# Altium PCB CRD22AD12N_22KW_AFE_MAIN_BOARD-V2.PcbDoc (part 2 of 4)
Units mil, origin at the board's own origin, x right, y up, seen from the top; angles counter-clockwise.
Board outline 14411 x 7330.3 mil, 4 copper layers (TOP, GND02, POWER03, BOTTOM), stack 78.531 mil thick; 589 components, 281 nets, 1401 pads, 282 vias.
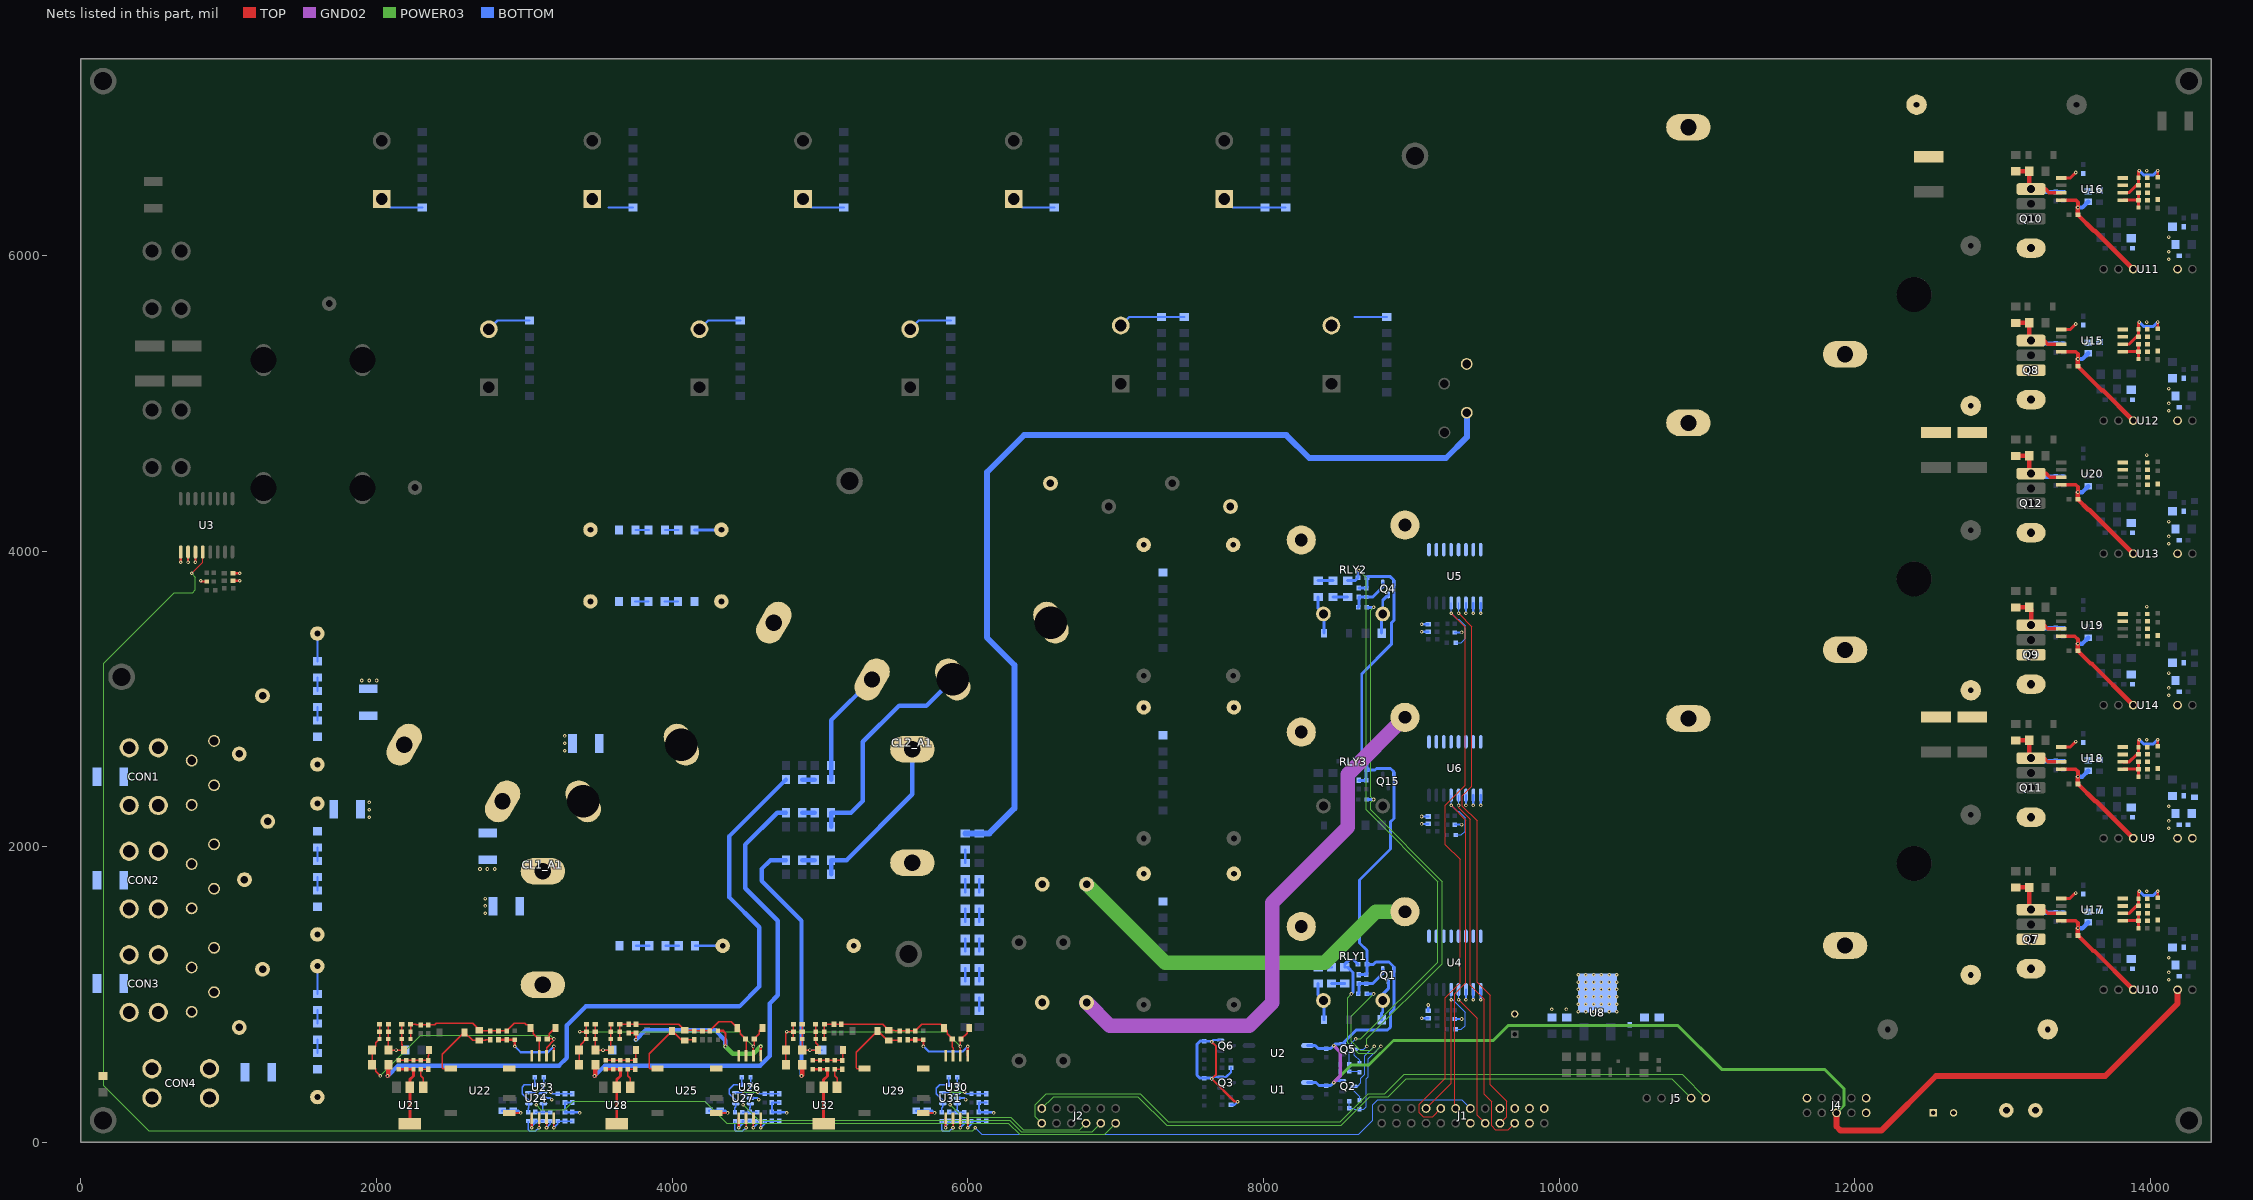
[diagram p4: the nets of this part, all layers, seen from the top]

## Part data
C1 C2 C3 C4 C5 C6 C37 C38 C39 C40 C41 C42 C43 C44 C56 C57 C58 C59 C60 C61 C62 C63 C64 C65 C66 C67 C68 C69 C70 C71 C72 C73 C74 C75 C76 C77 C78 C79 C80 C81 C82 C83 C84 C85 C86 C87 C88 C89 C90 C91 C92 C93 C94 C95 C96 C97 C98 C99 C100 C101 C102 C103 C104 C105 C106 C107 C108 C109 C112 C113 C114 C115 C116 C117 C119 C120 C121 C122 C123 C124 C126 C127 C128 C129 C130 C131 C133 C134 C135 C136 C137 C138 C140 C141 C142 C143 C144 C145 C147 C148 C149 C150 C151 C152 C212 C213 XC1 XC2 XC3 XC4 XC5 XC6 XC7 XC8 XC9 XC10 XC11 XC12 YC1 YC2 YC4 YC5 YC7 YC9 YC10 YC11: library part "CAP NP"
C7 C8 C9 C19 C20 C21 C32 C33 C34 C35 C36 C45 C46 C47 C48 C49 C50 C51 C52 C53 C54 C111 C118 C125 C132 C139 C146 C153 C154 C155 C156 C157 C158 C159 C160 C161 C162 C163 C164 C165 C166 C167 C168 C169 C170 C171 C172 C173 C174 C175 C176 C177 C178 C179 C180 C181 C182 C183 C184 C185 C186 C187 C188 C189 C190 C191 C192 C193 C194 C195 C196 C197 C198 C199 C200 C201 C202 C203 C204 C205 C206 C207 C208 C209 C210 C214 C215 C216 C217 C218 C219: library part "CAP NP_Dup1"
C10 C11 C13 C16 C17 C23 C24 C27 C28 C31 C55 C110: library part "CAP POL"
CL1: library part "TRNSFMR 67125450_0"
CL1_A1 CL2_A1: library part 126LNS_5
CON1 CON2 CON3 CON4 CON5 CON6: library part Connecter
D1 D2 D12 D13 D14 D15 D16 D17 D18: library part DIODE_0
D3 D5 D6 D8 D9 D11: library part BAS21/SOT_1
D4 D7 D10: library part "DIODE ZENER_0"
F1 F2 F3 F4 F5 F6 F7 F8: library part FUSE_0
J1: library part CON24A
J2: library part CON12A
J3: library part CON2
J4: library part CON10A
J5: library part CON5
L2 L3 L4: library part 126LNS_1
MT1 MT2 MT3 TP1 TP2: library part CON1_2
Q1 Q2 Q3 Q4 Q5 Q6 Q15: library part 2N7002/SOT
Q7 Q8 Q9 Q10 Q11 Q12: library part C3M0065090J_4
R1 R2 R3 R4 R5 R6 R7 R8 R9 R10 R11 R12 R13 R14 R15 R16 R17 R18 R19 R20 R21 R22 R23 R24 R25 R26 R27: library part R_2
R28 R29 R33 R34 R35 R36 R37 R38 R43 R44 R45 R46 R50 R51 R52 R53 R54 R55 R56 R57 R58 R59 R61 R62 R63 R64 R65 R66 R67 R68 R72 R73 R77 R78 R79 R80 R81 R83 R84 R89 R90 R92 R93 R94 R111 R112 R113 R114 R115 R116 R118 R119 R122 R123 R126 R127 R130 R131 R134 R136 R138 R139 R141 R142 R143 R144 R145 R146 R147 R148 R149 R150 R151 R152 R153 R154 R155 R156 R157 R158 R159 R160 R161 R162 R163 R164 R165 R166 R167 R168 R169 R170 R171 R172 R173 R174 R175 R176 R177 R178 R179 R181 R183 R184 R185 R186 R187 R188 R189 R190 R191 R198 R199 R200 R201 R202 R204 R205 R206 R207 R208 R209 R210 R211 R212 R213 R214 R215 R216 R217 R218 R219 R220 R221 R222 R223 R224 R225 R226 R227 R228 R229 R230 R231 R232 R233 R234 R235 R236 R237 R238 R239 R240 R241 R242 R243 R244 R245 R264 R265 R266 R267: library part RESISTOR
R42 R60 R203: library part RESISTOR_Dup1
R69 R70 R71 R74 R75 R76 R82 R85 R86 R87 R88 R91 R95 R96 R97 R98 R99 R100 R101 R102 R103 R104 R105 R106 R107 R108 R109 R110 R117 R120 R121 R124 R125 R128 R129 R132 R133 R135 R137 R140 R258 R259 R260 R261 R262 R263: library part R
RLY1 RLY2 RLY3: library part "RELAY SPST_1"
RV1 RV2 RV3 RV4 RV5 RV6 VAR1 VAR2 VAR3: library part VARISTOR
U1 U2: library part LEU169_TCLT1003_SOP-4L
U3 U4 U5 U6: library part MCR1101_0
U7 U8: library part MC78L05F-TP
U9 U10 U11 U12 U13 U14: library part E1212S-2WR2_3
U15 U16 U17 U18 U19 U20: library part UCC5350MC
U21 U28 U32: library part LT3092EST_SOT223_5
U22 U25 U29: library part PS_B0505XT
U23 U26 U30: library part 24C16BT-I/SN_3
U24 U27 U31: library part MCP6031
YC3 YC6 YC8: library part CAP

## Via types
v1: diameter 24/24/24/24 (per signal layer), hole 12, TOP to BOTTOM, tented both sides, 282 vias

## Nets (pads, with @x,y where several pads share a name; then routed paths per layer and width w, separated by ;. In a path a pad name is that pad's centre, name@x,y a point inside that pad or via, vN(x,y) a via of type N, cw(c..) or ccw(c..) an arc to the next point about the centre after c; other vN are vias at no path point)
-3V_PFCHA: C71.2 C72.2 C129.2 C131.2 U10.5 U17.8 | length 817.5
  TOP w25: U17.8@13396.68,1500 13495.34,1500 13510.26,1485.08 v1(13510.26,1450)
  TOP w30: v1(13510.26,1450) C131.2@13510.26,1400 13615.11,1295.15 13622.17,1295.15 U10.5@13884.25,1033.07
  BOTTOM w30: v1(13510.26,1450) 13540.38,1450 C129.2@13580.34,1489.96
-3V_PFCHB: C88.2 C90.2 C115.2 C117.2 U12.5 U15.8 | length 817.5
  TOP w25: U15.8@13396.68,5350 13495.34,5350 13510.26,5335.08 v1(13510.26,5300)
  TOP w30: v1(13510.26,5300) C117.2@13510.26,5250 13670.26,5090 13677.32,5090 U12.5@13884.25,4883.07
  BOTTOM w30: v1(13510.26,5300) 13540.38,5300 C115.2@13580.34,5339.96
-3V_PFCHC: C106.2 C108.2 C143.2 C145.2 U14.5 U19.8 | length 813.8
  TOP w25: U19.8@13396.68,3425 13489.04,3425 13510.26,3403.79 v1(13510.26,3375)
  TOP w30: v1(13510.26,3375) C145.2@13510.26,3325 13595.26,3240 13602.32,3240 U14.5@13884.25,2958.07
  BOTTOM w30: v1(13510.26,3375) 13540.38,3375 C143.2@13580.34,3414.96
-3V_PFCLA: C70.2 C73.2 C136.2 C138.2 U9.5 U18.8 | length 817.5
  TOP w25: U18.8@13396.68,2525 13495.34,2525 13510.26,2510.08 v1(13510.26,2475)
  TOP w30: v1(13510.26,2475) C138.2@13510.26,2425 13627.62,2307.64 13634.68,2307.64 U9.5@13884.25,2058.07
  BOTTOM w30: v1(13510.26,2475) 13540.38,2475 C136.2@13580.34,2514.96
-3V_PFCLB: C89.2 C91.2 C122.2 C124.2 U11.5 U16.8 | length 817.5
  TOP w25: U16.8@13396.68,6375 13495.34,6375 13510.26,6360.08 v1(13510.26,6325)
  TOP w30: v1(13510.26,6325) C124.2@13510.26,6275 13617.62,6167.64 13624.68,6167.64 U11.5@13884.25,5908.07
  BOTTOM w30: v1(13510.26,6325) 13540.38,6325 C122.2@13580.34,6364.96
-3V_PFCLC: C107.2 C109.2 C150.2 C152.2 U13.5 U20.8 | length 817.5
  TOP w25: U20.8@13396.68,4450 13495.34,4450 13510.26,4435.08 v1(13510.26,4400)
  TOP w30: v1(13510.26,4400) C152.2@13510.26,4350 13580.12,4280.14 13587.18,4280.14 U13.5@13884.25,3983.07
  BOTTOM w30: v1(13510.26,4400) 13540.38,4400 C150.2@13580.34,4439.96
AC_LA: CL2_A1.6 R21.2 R28.1 R266.1 RLY1.3 RV1.2 XC9.1 XC10.1 | length 792.3
  BOTTOM w30: R28.1@5075.12,2455 R266.1@5075.12,2550 5075.12,2855.36 CL2_A1.6@5352.24,3132.48
AC_LA1: RLY1.4 RV2.1 U4.1 U4.2 U4.3 U4.4 | length 2516.8
  POWER03 w100: RV2.1@6803.74,1746.85 7335.59,1215 8415,1215 8761.07,1561.07 RLY1.4@8956.88,1561.07
AC_LA_ADC: J1.15 U4.12 | length 979.3
  TOP w6: v1(9320,965) 9445,840 9445,185 J1.15@9500,130
  BOTTOM w6: v1(9320,965) U4.12@9320,1034.76
AC_LA_OC: J1.8 R100.2 U4.13 | length 1170.2
  TOP w6: J1.8@9100,230 9270,400 v1(9270,965)
  BOTTOM w6: U4.13@9270,1034.76 v1(9270,965) 9280,965 9365,880 9365,791 9339,765 R100.2@9299.92,765
AC_LA_SAMP: R29.2 R146.1 | length 4615.9
  TOP w30: v1(2075,450) 2080.12,455.12 R146.1@2080.12,525
  BOTTOM w30: v1(2075,450) 2145,520 3235,520 3288,573 3288,793 3415,920 4455,920 4590,1055 4590,1455 4385,1660 4385,2070.12 R29.2@4769.88,2455
AC_LAB_G: C157.1 C158.1 C159.1 C160.1 C161.1 C164.1 C166.2 C171.2 D4.1 R155.1 R156.1 U22.3 U23.3 U23.4 | length 1187.4
  TOP w10: R155.1@2229.92,700 R156.1@2229.92,750 C171.2@2229.92,800 2265,800 2270.08,794.92 C159.1@2299.99,794.92 C160.1@2350,794.92 2394.92,794.92 2405,805 2650.04,805 2700.12,754.92 C164.1@2769.99,754.92 C158.1@2825,754.92 C157.1@2880,754.92 2930.08,805 3004.21,805 3012.85,796.36 3025.27,796.36 3040.35,781.28 D4.1@3040.35,775 3060,755.35 3060,735.08 C166.2@3095.08,700 3099.84,695.24 U23.3@3099.84,586.52
AC_LAB_SENSE: C166.1 C167.1 C168.1 D4.2 R146.2 R152.2 R153.2 U23.2 | length 1969.9
  TOP w10: C167.1@2020.08,800 C168.1@2020.08,750 R153.2@2020.08,700 1995,674.92 1995,650.12 R152.2@1969.88,625 R146.2@1969.88,525 1995,499.88 1995,480 v1(2025,450) ; U23.2@3149.84,586.52 3149.84,639.84 3200,690 v1(3200,700) C166.1@3154.92,700 3170,715.08 3170,735.35 D4.2@3209.65,775
  POWER03 w6: v1(2025,450) 2300,725 3175,725 v1(3200,700)
AC_LAB_SENSE_ADC: C214.2 J2.2 R154.2 U24.1 | length 4300
  POWER03 w6: v1(3080,255) 3112.5,222.5 3272.5,222.5 3330,280 4220,280 4370,130 6275,130 6350,55 6925,55 J2.2@7000,130
  BOTTOM w10: v1(3080,255) 3080,310 3107.4,337.4 U24.1@3129.21,337.4 3129.92,338.11 C214.2@3129.92,390 R154.2@3129.92,440
AC_LAP: L2.3 U4.5 U4.6 U4.7 U4.8
AC_LB: CL2_A1.4 R12.2 R37.1 R264.1 RLY2.3 RV3.2 XC6.1 XC11.1 | length 1525.8
  BOTTOM w30: R264.1@5075.12,2135 R37.1@5075.12,2230 5210,2230 5290,2310 5290,2710 5535,2955 5720.28,2955 CL2_A1.4@5897.76,3132.48
AC_LB1: RLY2.4 RV4.1 U5.1 U5.2 U5.3 U5.4
AC_LB_ADC: J1.17 U5.12 | length 3726.9
  TOP w6: v1(9320,3580) 9410,3490 9410,2410 9345,2345 9345,2275 9445,2175 9445,1085 9535,995 9535,390 9645,280 9645,175 J1.17@9600,130
  BOTTOM w6: v1(9320,3580) U5.12@9320,3649.76
AC_LB_OC: J1.10 R105.2 U5.13 | length 4173.6
  TOP w6: J1.10@9200,230 9145,175 9080,175 9055,200 9055,260 9230,435 9230,980 9330,1080 9330,1915 9230,2015 9230,2280 9365,2415 9365,3485 v1(9270,3580)
  BOTTOM w6: U5.13@9270,3649.76 v1(9270,3580) 9310,3540 9320,3540 9365,3495 9365,3406 9339,3380 R105.2@9299.92,3380
AC_LB_SAMP: R38.2 R163.1 | length 3225.9
  TOP w30: v1(3475,450) 3480.12,455.12 R163.1@3480.12,525
  BOTTOM w30: v1(3475,450) 3545,520 4595,520 4660,585 4660,940 4715,995 4715,1500 4495,1720 4495,2015 4710,2230 R38.2@4769.88,2230
AC_LBC_G: C172.1 C173.1 C174.1 C177.1 C180.2 C181.1 C182.1 C193.2 D7.1 R175.1 R176.1 U25.3 U26.3 U26.4 | length 1168.7
  TOP w10: R175.1@3644.92,700 C193.2@3644.92,800 3704.92,800 C172.1@3704.99,799.92 C173.1@3755,799.92 4045.12,799.92 C174.1@4085,760.04 4144.88,760.04 C177.1@4149.99,754.92 C182.1@4205,754.92 C181.1@4254.99,754.92 4315.08,815 4400.35,815 D7.1@4440.35,775 4460,755.35 4460,735.08 4499.84,695.24 U26.3@4499.84,586.52
AC_LBC_SENSE: C180.1 C186.1 C187.1 D7.2 R163.2 R169.2 R170.2 U26.2 | length 1770.4
  TOP w10: R163.2@3369.88,525 R169.2@3369.88,625 3380,635.12 3380,659.92 R170.2@3420.08,700 C187.1@3420.08,750 ; v1(3375,750) C187.1@3420.08,750 ; C186.1@3420.08,800 C187.1@3420.08,750 ; U26.2@4549.84,586.52 v1(4549.84,650) 4554.92,655.08 C180.1@4554.92,700 4590,735.08 4590,755.35 D7.2@4609.65,775
  POWER03 w6: v1(3375,750) 4449.84,750 v1(4549.84,650)
AC_LBC_SENSE_ADC: C217.2 J2.4 R164.2 U27.1 | length 2736.2
  POWER03 w6: v1(4480,255) 4585,150 6283.28,150 6362.28,71 6841,71 J2.4@6900,130
  BOTTOM w10: v1(4480,255) 4480,305 4512.4,337.4 U27.1@4529.21,337.4 4529.92,338.11 C217.2@4529.92,390 R164.2@4529.92,440
AC_LBP: L3.3 U5.5 U5.6 U5.7 U5.8
AC_LC: CL2_A1.2 R3.2 R45.1 R265.1 RLY3.3 RV6.2 XC3.1 XC12.1 | length 1134.2
  BOTTOM w30: R265.1@5075.12,1815 R45.1@5075.12,1910 5180,1910 5625,2355 CL2_A1.2@5625,2660.04
AC_LC1: RLY3.4 RV5.1 U6.1 U6.2 U6.3 U6.4 | length 3688.2
  GND02 w100: RV5.1@6803.74,946.85 6961.59,789 7903,789 8060,946 8060,1622 8570,2132 8570,2489.18 RLY3.4@8956.88,2876.06
AC_LC_ADC: J1.19 U6.12 | length 2514
  TOP w6: v1(9320,2280) 9320,2265 9400,2185 9400,1065 9495,970 9495,325 9545,275 9545,111.5 9569,87.5 9657.5,87.5 J1.19@9700,130
  BOTTOM w6: v1(9320,2280) U6.12@9320,2349.76
AC_LC_OC: J1.12 R108.2 U6.13 | length 2489.4
  TOP w6: v1(9270,2280) 9370,2180 9370,1080 9295,1005 9295,235 J1.12@9300,230
  BOTTOM w6: U6.13@9270,2349.76 v1(9270,2280) 9310,2240 9320,2240 9365,2195 9365,2106 9339,2080 R108.2@9299.92,2080
AC_LC_SAMP: R46.2 R181.1 | length 1778.7
  TOP w30: v1(4875,450) 4880.12,455.12 R181.1@4880.12,525
  BOTTOM w30: R46.2@4769.88,1910 4665,1910 4605,1850 4605,1770 4875,1500 v1(4875,450)
AC_LCA_G: C188.1 C189.1 C190.1 C194.1 C197.2 C198.1 C199.1 C203.2 D10.1 R189.1 R190.1 U29.3 U30.3 U30.4 | length 1171.3
  TOP w10: R189.1@5029.92,700 R190.1@5029.92,750 C203.2@5029.92,800 5094.92,800 C198.1@5094.99,799.92 C199.1@5145,799.92 5425.12,799.92 C190.1@5465,760.04 5503.07,760.04 5508.19,754.92 C189.1@5595,754.92 C188.1@5644.99,754.92 5690.08,800 5815.35,800 D10.1@5840.35,775 5860,755.35 5860,735.08 C197.2@5895.08,700 5895.08,644.92 5899.84,640.16 U30.3@5899.84,586.52
AC_LCA_SENSE: C197.1 C201.1 C202.1 D10.2 R181.2 R187.2 R188.2 U30.2 | length 1801.7
  TOP w10: R181.2@4769.88,525 R187.2@4769.88,625 4769.88,744.88 v1(4775,750) C202.1@4820.08,750 ; R188.2@4820.08,700 C202.1@4820.08,750 ; C201.1@4820.08,800 C202.1@4820.08,750 ; U30.2@5949.84,586.52 v1(5949.84,650) 5949.84,694.92 C197.1@5954.92,700 5995,740.08 5995,760.35 D10.2@6009.65,775
  POWER03 w6: v1(4775,750) 5849.84,750 v1(5949.84,650)
AC_LCA_SENSE_ADC: C219.2 J2.6 R179.2 U31.1 | length 1225.4
  POWER03 w6: v1(5880,255) 5965,170 6291.57,170 6374.07,87.5 6757.5,87.5 J2.6@6800,130
  BOTTOM w10: v1(5880,255) 5880,310 5907.4,337.4 U31.1@5929.21,337.4 5929.21,389.29 C219.2@5929.92,390 R179.2@5929.92,440
AC_LCP: L4.3 U6.5 U6.6 U6.7 U6.8
AGND: C3.2 C6.2 C37.2 C38.2 C39.2 C40.2 C41.2 C42.2 C43.2 C44.2 C47.1 C48.1 C52.1 C53.1 C54.1 C55.2 C111.2 C112.2 C113.2 C114.2 C118.2 C119.2 C120.2 C121.2 C125.2 C126.2 C127.2 C128.2 C132.2 C133.2 C134.2 C135.2 C139.2 C140.2 C141.2 C142.2 C146.2 C147.2 C148.2 C149.2 C153.2 C154.2 C155.1 C156.1 C162.2 C163.2 C169.1 C170.1 C175.2 C176.2 C178.2 C179.2 C183.1 C184.1 C191.2 C192.2 C195.2 C196.2 C215.2 C216.2 C218.2 J1.13 J1.18 J1.20 J1.21 J1.22 J1.24 J4.9 Q3.2 Q6.2 R59.1 R68.1 R101.2 R102.2 R109.2 R110.2 R119.2 R123.2 R127.2 R131.2 R136.2 R139.2 R144.2 R160.2 R173.2 U3.9 U3.10 U3.11 U4.9 U4.10 U4.11 U5.9 U5.10 U5.11 U6.9 U6.10 U6.11 U8.2 U15.3 U15.4 U16.3 U16.4 U17.3 U17.4 U18.3 U18.4 U19.3 U19.4 U20.3 U20.4 U22.1 U23.5 U24.2 U25.1 U26.5 U27.2 U29.1 U30.5 U31.2 | length 4572.4
  TOP w15: v1(675,3925) U3.9@675,3994.76 ; v1(725,3925) U3.10@725,3994.76 ; v1(775,3925) U3.11@775,3994.76 ; v1(810,3800) 814.92,3795.08 R101.2@850,3795.08 ; C37.2@1029.92,3800 v1(1075,3800) ; C38.2@1029.92,3850 v1(1075,3850) ; U22.1@2898.5,200 v1(2975,200) ; v1(3049.84,100.16) U23.5@3049.84,163.48 ; U25.1@4298.5,200 v1(4375,200) ; v1(4449.84,100.16) U26.5@4449.84,163.48 ; U29.1@5698.5,200 v1(5775,200) ; v1(5849.84,100.16) U30.5@5849.84,163.48 ; v1(7650,680) 7680,650 7680,460 v1(7650,430) 7803.64,276.36 7823.64,276.36 v1(7825,275)
  BOTTOM w15: C155.1@2850,214.96 C156.1@2925,214.96 2960.04,214.96 v1(2975,200) ; v1(3049.84,100.16) 3049.84,111.84 3075,137 C215.2@3075,145.08 R144.2@3125,145.08 ; U24.2@3129.21,300 3175,300 v1(3185,290) ; C154.2@3325,270.08 C153.2@3275,270.08 C163.2@3275,204.92 C162.2@3325,204.92 3370.08,204.92 v1(3375,200) ; C170.1@4250,214.96 C169.1@4325,214.96 4360.04,214.96 v1(4375,200) ; v1(4449.84,100.16) 4475,125.32 R160.2@4475,145.08 C216.2@4525,145.08 ; U27.2@4529.21,300 4575,300 v1(4585,290) ; C176.2@4725,270.08 C175.2@4675,270.08 C179.2@4675,204.92 C178.2@4725,204.92 4770.08,204.92 v1(4775,200) ; C184.1@5650,214.96 C183.1@5725,214.96 5760.04,214.96 v1(5775,200) ; v1(5849.84,100.16) 5849.84,112.84 5875,138 C218.2@5875,145.08 R173.2@5925,145.08 ; U31.2@5929.21,300 5975,300 v1(5985,290) ; C192.2@6125,270.08 C191.2@6075,270.08 C196.2@6075,204.92 C195.2@6125,204.92 6170.08,204.92 v1(6175,200) ; R68.1@7600,684.92 7645.08,684.92 v1(7650,680) 7662.4,692.4 Q6.2@7710.24,692.4 ; v1(7650,430) 7662.4,442.4 Q3.2@7710.24,442.4 7747.4,442.4 7779.92,474.92 C6.2@7779.92,505 ; C3.2@7779.92,255 7805,255 v1(7825,275) ; v1(9070,840) C39.2@9115.08,840 ; v1(9070,2155) C43.2@9115.08,2155 ; v1(9070,2205) C44.2@9115.08,2205 ; v1(9070,3455) C41.2@9115.08,3455 ; v1(9070,3505) C42.2@9115.08,3505 ; C40.2@9115.08,890 v1(9115.08,930) ; R102.2@9295,835.08 v1(9340.08,835.08) ; R110.2@9295,2150.08 v1(9340.08,2150.08) ; R109.2@9295,3450.08 v1(9340.08,3450.08) ; v1(9370,965) U4.11@9370,1034.76 ; v1(9370,2280) U6.11@9370,2349.76 ; v1(9370,3580) U5.11@9370,3649.76 ; v1(9420,965) U4.10@9420,1034.76 ; v1(9420,2280) U6.10@9420,2349.76 ; v1(9420,3580) U5.10@9420,3649.76 ; v1(9470,965) U4.9@9470,1034.76 ; v1(9470,2280) U6.9@9470,2349.76 ; v1(9470,3580) U5.9@9470,3649.76
  BOTTOM w20: R68.1@7600,684.92 7570,684.92 7550,664.92 7550,454.92 7570,434.92 R59.1@7600,434.92 7645.08,434.92 v1(7650,430)
  other v1: 10130,885 10180,885 10235,885 10285,885 10340,885 10390,885 9950,900 10050,900 10130,935 10180,935 10235,935 10285,935 10340,935 10390,935 10130,985 10180,985 10235,985 10285,985 10340,985 10390,985 10130,1035 10180,1035 10235,1035 10285,1035 10340,1035 10390,1035 10130,1085 10180,1085 10235,1085 10285,1085 10340,1085 10390,1085 10130,1135 10180,1135 10235,1135 10285,1135 10340,1135 10390,1135 13975,1700 13975,2725 13975,3625 13975,4650 13975,5550 13975,6575
CAN5V_GND: J2.11 J5.2 | length 4691.3
  POWER03 w6: J2.11@6500,230 6580,310 7150,310 7345,115 8525.54,115 8720.54,310 8844.64,310 8964.64,430 10763.11,430 J5.2@10893.11,300
CAN_5V: J2.12 J5.1 | length 4990.3
  POWER03 w6: J2.12@6500,130 6455,175 6455,255 6530,330 7165,330 7355,140 8520,140 8710,330 8822.22,330 8952.22,460 10833.11,460 J5.1@10993.11,300
CLAMPHA: C7.1 Q7.4 R69.2 R74.2 R258.1 U17.7 | length 685.9
  TOP w25: Q7.4@13192.96,1575 13280.68,1575 13305.68,1550 U17.7@13396.68,1550
  TOP w30: R258.1@13090,1724.88 13090.12,1725 R69.2@13180.56,1725 13180.56,1587.4 Q7.4@13192.96,1575
  BOTTOM w30: Q7.4@13192.96,1575 13213.04,1554.92 13310.68,1554.92 C7.1@13360.68,1554.92 R74.2@13410.68,1554.92
CLAMPHB: C8.1 Q8.4 R70.2 R75.2 R261.1 U15.7 | length 655.9
  TOP w25: Q8.4@13192.96,5425 13280,5425 13305,5400 U15.7@13396.68,5400
  TOP w30: R261.1@13090,5544.88 13150,5544.88 13180.44,5544.88 R70.2@13180.56,5545 13180.56,5437.4 Q8.4@13192.96,5425
  BOTTOM w30: Q8.4@13192.96,5425 13213.04,5404.92 13310.68,5404.92 C8.1@13360.68,5404.92 R75.2@13410.68,5404.92
CLAMPHC: C9.1 Q9.4 R71.2 R76.2 R262.1 U19.7 | length 655.9
  TOP w25: Q9.4@13192.96,3500 13280.68,3500 13305.68,3475 U19.7@13396.68,3475
  TOP w30: R262.1@13090,3619.88 13180.44,3619.88 R71.2@13180.56,3620 13192.96,3607.6 Q9.4@13192.96,3500
  BOTTOM w30: Q9.4@13192.96,3500 13213.04,3479.92 C9.1@13360.68,3479.92 R76.2@13410.68,3479.92
CLAMPLA: C36.1 Q11.4 R86.2 R91.2 R259.1 U18.7 | length 655.9
  TOP w25: Q11.4@13192.96,2600 13280.68,2600 13305.68,2575 U18.7@13396.68,2575
  TOP w30: R259.1@13090,2719.88 13090.11,2720 R86.2@13180.56,2720 13180.56,2612.4 Q11.4@13192.96,2600
  BOTTOM w30: Q11.4@13192.96,2600 13213.04,2579.92 13300.68,2579.92 C36.1@13360.68,2579.92 R91.2@13410.68,2579.92
CLAMPLB: C34.1 Q10.4 R82.2 R87.2 R260.1 U16.7 | length 655.9
  TOP w25: Q10.4@13192.96,6450 13290,6450 13315,6425 U16.7@13396.68,6425
  TOP w30: R260.1@13090,6569.88 13090.12,6570 R82.2@13180.56,6570 13180.56,6462.4 Q10.4@13192.96,6450
  BOTTOM w30: Q10.4@13192.96,6450 13213.04,6429.92 13310.68,6429.92 C34.1@13360.68,6429.92 R87.2@13410.68,6429.92
CLAMPLC: C35.1 Q12.4 R85.2 R88.2 R263.1 U20.7 | length 655.9
  TOP w25: Q12.4@13192.96,4525 13295,4525 13320,4500 U20.7@13396.68,4500
  TOP w30: R263.1@13090,4644.88 13180.44,4644.88 R85.2@13180.56,4645 13180.56,4537.4 Q12.4@13192.96,4525
  BOTTOM w30: Q12.4@13192.96,4525 13213.04,4504.92 13310.68,4504.92 13336.07,4504.92 C35.1@13360.68,4504.92 R88.2@13410.68,4504.92
DC_14V_INPUT: C110.1 J3.2 J4.1
GGND: C1.2 C2.1 C4.2 C5.1 C62.2 C63.2 C64.2 C65.2 C66.2 C67.2 C68.2 C69.2 C78.2 C79.2 C82.2 C83.2 C84.2 C85.2 C86.2 C87.2 C96.2 C97.2 C100.2 C101.2 C102.2 C103.2 C104.2 C105.2 C212.1 C213.2 J4.6 Q1.2 Q2.2 Q4.2 Q5.2 Q15.2 R44.2 R53.1 R62.2 R66.1 R198.2 U1.3 U2.3 U9.2 U10.2 U11.2 U12.2 U13.2 U14.2 | length 12195.1
  TOP w40: J4.6@11877.21,200 11877.21,107.79 11905,80 12180,80 12550,450 13695,450 14184.25,939.25 U10.2@14184.25,1033.07
  GND02 w25: v1(8475,405) 8520,450 8520,610 v1(8475,655)
  POWER03 w20: v1(8475,405) 8595,525 8715,525 8880,690 9555,690 9655,790 10805,790 11100,495 11795,495 11926.71,363.29 11926.71,249.5 J4.6@11877.21,200
  BOTTOM w20: U1.3@8297.83,405 8355,405 8375.08,384.92 R53.1@8425,384.92 8454.92,384.92 v1(8475,405) 8487.4,417.4 Q2.2@8535.24,417.4 ; U2.3@8297.83,655 8350,655 8370.08,634.92 R66.1@8425,634.92 8454.92,634.92 v1(8475,655) 8487.4,667.4 Q5.2@8535.24,667.4 8627.83,760 8840,760 8860,780 8860,880 8882.4,902.4 Q1.2@8882.4,1169.76 8882.4,1187.6 8850,1220 8760,1220 8745,1205 C1.2@8699.92,1205 ; C2.1@8645,1134.92 R44.2@8695,1134.92 8699.92,1139.84 C1.2@8699.92,1205 ; C212.1@8645,2449.92 R198.2@8695,2449.92 8695,2515.08 C213.2@8699.92,2520 ; C5.1@8645,3749.92 R62.2@8695,3749.92 8699.92,3754.84 C4.2@8699.92,3820 8709.92,3830 8855,3830 8882.4,3802.6 Q4.2@8882.4,3784.76 8882.4,3532.4 8865,3515 8865,3370 8665,3170 8665,2640 8699.92,2605.08 C213.2@8699.92,2520 ; C1.2@8699.92,1205 8699.92,1300.08 8650,1350 8650,1775 8860,1985 8860,2170 8882.4,2192.4 Q15.2@8882.4,2484.76 8882.4,2507.6 8860,2530 8765,2530 8755,2520 C213.2@8699.92,2520
  other v1: 14125,1100 14125,1150 14125,1250 14125,2125 14125,2175 14125,2275 14125,3025 14125,3075 14125,3175 14125,4050 14125,4100 14125,4200 14125,4950 14125,5000 14125,5100 14125,5975 14125,6025 14125,6125
GND_EARTH: CON4.1 CON4.2 CON4.3 CON4.4 R267.1 YC1.2 YC2.2 YC3.2 YC4.2 YC5.2 YC6.2 YC7.2 YC8.2 YC9.2
  other v1: 2735,1550 2735,1600 2735,1650 2700,1850 2750,1850 2800,1850 1950,2200 1950,2250 1950,2300 3273,2650 3273,2700 3273,2750 1900,3125 1950,3125 2000,3125
IGND: C110.2 J3.1 J4.2
IOUT_ADC: J1.14 U3.12 | length 13565.4
  TOP w6: v1(750,3850) 825,3925 U3.12@825,3994.76
  POWER03 w6: v1(750,3850) 775,3825 775,3740 755,3720 633,3720 155,3242 155,383.28 458.28,80 6035,80 6050,95 v1(6050,100)
  BOTTOM w6: v1(6050,100) 6095,55 8645,55 8740,150 8740,255 8775,290 9340,290 J1.14@9400,230
LA: CON1.1 CON1.2 CON1.3 CON1.4 F1.1 F2.1 YC1.1
LAB_G: C167.2 C168.2 C171.1 D5.2 R152.1 R153.1 R155.2 R156.2 R240.2 | length 524.5
  TOP w10: C167.2@2079.92,800 C168.2@2079.92,750 R153.1@2079.92,700 2080.12,699.8 R152.1@2080.12,625 v1(2132,625) D5.2@2185.35,625 2173.3,637.05 2173.3,661.7 2170.08,664.92 R156.2@2170.08,750 C171.1@2170.08,800
  BOTTOM w6: v1(2132,625) R240.2@2194.88,625
LB: CON2.1 CON2.2 CON2.3 CON2.4 F3.1 F4.1 YC4.1
LBC_G: C186.2 C187.2 C193.1 D9.2 R169.1 R170.1 R175.2 R176.2 R241.2 | length 518.3
  TOP w10: C186.2@3479.92,800 C187.2@3479.92,750 R170.1@3479.92,700 3480.12,699.8 R169.1@3480.12,625 v1(3532,625) D9.2@3585.35,625 3585.35,699.73 R175.2@3585.08,700 R176.2@3585.08,750 C193.1@3585.08,800
  BOTTOM w10: v1(3532,625) R241.2@3594.88,625
LC: CON3.1 CON3.2 CON3.3 CON3.4 F5.1 F6.1 YC7.1
LCA_G: C201.2 C202.2 C203.1 D11.2 R187.1 R188.1 R189.2 R190.2 R242.2 | length 544.5
  TOP w10: C201.2@4879.92,800 C202.2@4879.92,750 R188.1@4879.92,700 4880.12,699.8 R187.1@4880.12,625 v1(4932,625) D11.2@4985.35,625 4985.35,659.65 4970.08,674.92 R189.2@4970.08,700 R190.2@4970.08,750 C203.1@4970.08,800
  BOTTOM w10: v1(4932,625) R242.2@5014.88,625
N17200031: C165.1 R147.2 U21.1 | length 177.5
  TOP w10: U21.1@2315.55,374.02 2315.55,434.45 2300,450 R147.2@2300,495.08 C165.1@2350,495.08
N17200043: C165.2 D5.1 R147.1 R148.1 R149.1 R150.1 | length 272
  TOP w10: R149.1@2150,554.92 R148.1@2200,554.92 R150.1@2250,554.92 R147.1@2300,554.92 C165.2@2350,554.92 2350,585 2354.65,589.65 D5.1@2354.65,625
N17200052: R148.2 R149.2 R150.2 U21.2 U21.4 | length 479.5
  TOP w20: R149.2@2150,495.08 R148.2@2200,495.08 R150.2@2250,495.08 2250,450 2225,425 U21.2@2225,374.02 U21.4@2225,125.98
N17202885: C185.1 R165.2 U28.1 | length 177.5
  TOP w10: U28.1@3715.55,374.02 3715.55,434.45 3700,450 R165.2@3700,495.08 C185.1@3750,495.08
N17202901: C185.2 D9.1 R165.1 R166.1 R167.1 R168.1 | length 272
  TOP w10: R167.1@3550,554.92 R166.1@3600,554.92 R168.1@3650,554.92 R165.1@3700,554.92 C185.2@3750,554.92 3754.65,559.57 D9.1@3754.65,625
N17202907: R166.2 R167.2 R168.2 U28.2 U28.4 | length 479.5
  TOP w20: R167.2@3550,495.08 R166.2@3600,495.08 R168.2@3650,495.08 3650,450 3625,425 U28.2@3625,374.02 U28.4@3625,125.98
N17203702: C200.1 R183.2 U32.1 | length 177.5
  TOP w10: U32.1@5115.55,374.02 5115.55,434.45 5100,450 R183.2@5100,495.08 C200.1@5150,495.08
N17203726: R184.2 R185.2 R186.2 U32.2 U32.4 | length 479.5
  TOP w20: R185.2@4950,495.08 R184.2@5000,495.08 R186.2@5050,495.08 5050,450 5025,425 U32.2@5025,374.02 U32.4@5025,125.98
N17203738: C200.2 D11.1 R183.1 R184.1 R185.1 R186.1 | length 272
  TOP w10: R185.1@4950,554.92 R184.1@5000,554.92 R186.1@5050,554.92 R183.1@5100,554.92 C200.2@5150,554.92 5154.65,559.57 D11.1@5154.65,625
N17207655: C157.2 C158.2 R142.2 U23.1 | length 516.3
  TOP w15: C158.2@2825,695.08 C157.2@2880,695.08 R142.2@2935,695.08 v1(2935,650) ; U23.1@3199.84,586.52 v1(3199.84,649.84)
  BOTTOM w15: v1(2935,650) 2975,610 3160,610 v1(3199.84,649.84)
N17208388: C162.1 C163.1 R143.2 U23.8 | length 218.7
  TOP w10: v1(3199.84,100.16) U23.8@3199.84,163.48
  BOTTOM w10: v1(3199.84,100.16) 3225,125.32 R143.2@3225,145.08 C163.1@3275,145.08 C162.1@3325,145.08
N17208484: R145.1 U23.7 | length 118.7
  TOP w10: v1(3149.84,100.16) U23.7@3149.84,163.48
  BOTTOM w10: v1(3149.84,100.16) 3175,125.32 R145.1@3175,145.08
N17208491: R151.1 U23.6 | length 212.8
  TOP w10: v1(3099.84,100.16) U23.6@3099.84,163.48
  BOTTOM w10: R151.1@3025,145.08 3025,85 3035,75 3074.68,75 v1(3099.84,100.16)
N17208678: C214.1 R151.2 R154.1 U24.4 | length 332.7
  BOTTOM w10: R151.2@3025,204.92 3025,230 3030.78,235.79 U24.4@3030.78,262.6 3030.78,284.22 2985,330 2985,375 3000,390 C214.1@3070.08,390 R154.1@3070.08,440
N17208781: C153.1 C154.1 R141.2 U24.5 | length 309.3
  POWER03 w10: v1(3080,350) 3170,350 v1(3180,340)
  BOTTOM w10: U24.5@3030.78,337.4 3070,337.4 3080,347.4 v1(3080,350) ; v1(3180,340) 3190.08,329.92 R141.2@3225,329.92 C153.1@3275,329.92 C154.1@3325,329.92
N17209770: C172.2 C173.2 R158.2 U26.1 | length 1286.7
  TOP w15: C172.2@3704.99,740.08 C173.2@3755,740.08 v1(3755,695) ; R158.2@4310,754.92 4345.08,754.92 4360,740 v1(4360,650) ; U26.1@4599.84,586.52 v1(4599.84,649.84)
  POWER03 w30: v1(4360,650) 4410,600 4550,600 v1(4599.84,649.84)
  BOTTOM w30: v1(3755,695) 3820,760 4290,760 4360,690 v1(4360,650)
N17209888: C178.1 C179.1 R159.2 U26.8 | length 218.7
  TOP w10: v1(4599.84,100.16) U26.8@4599.84,163.48
  BOTTOM w10: v1(4599.84,100.16) 4625,125.32 R159.2@4625,145.08 C179.1@4675,145.08 C178.1@4725,145.08
N17209896: R161.1 U26.7 | length 118.7
  TOP w10: v1(4549.84,100.16) U26.7@4549.84,163.48
  BOTTOM w10: v1(4549.84,100.16) 4575,125.32 R161.1@4575,145.08
N17209898: R162.1 U26.6 | length 212.8
  TOP w10: v1(4499.84,100.16) U26.6@4499.84,163.48
  BOTTOM w10: R162.1@4425,145.08 4425,85 4435,75 4474.68,75 v1(4499.84,100.16)
N17209922: C216.1 R160.1 R161.2 U27.3 | length 159.4
  BOTTOM w10: R160.1@4475,204.92 C216.1@4525,204.92 ; U27.3@4529.21,262.6 4529.21,239.21 4525,235 C216.1@4525,204.92 ; R161.2@4575,204.92 C216.1@4525,204.92
N17209924: C217.1 R162.2 R164.1 U27.4 | length 323.9
  BOTTOM w10: R162.2@4425,204.92 4425,235 4430.78,240.79 U27.4@4430.78,262.6 4430.78,284.22 4385,330 4385,360 4415,390 C217.1@4470.08,390 R164.1@4470.08,440
N17209942: C175.1 C176.1 R157.2 U27.5 | length 303.7
  POWER03 w10: v1(4480,345) 4485.13,339.87 4579.87,339.87 v1(4580,340)
  BOTTOM w10: U27.5@4430.78,337.4 4472.4,337.4 v1(4480,345) ; v1(4580,340) 4590.08,329.92 R157.2@4625,329.92 C175.1@4675,329.92 C176.1@4725,329.92
N17210692: C188.2 C189.2 R171.2 U30.1 | length 542.2
  TOP w15: C189.2@5595,695.08 C188.2@5644.99,695.08 R171.2@5700,695.08 v1(5700,650) ; U30.1@5999.84,586.52 v1(5999.84,649.84)
  BOTTOM w15: v1(5700,650) 5735,615 5965,615 v1(5999.84,649.84)
N17210810: C195.1 C196.1 R174.2 U30.8 | length 218.7
  TOP w10: v1(5999.84,100.16) U30.8@5999.84,163.48
  BOTTOM w10: v1(5999.84,100.16) 6025,125.32 R174.2@6025,145.08 C196.1@6075,145.08 C195.1@6125,145.08
N17210816: R177.1 U30.7 | length 118.7
  TOP w10: v1(5949.84,100.16) U30.7@5949.84,163.48
  BOTTOM w10: v1(5949.84,100.16) 5975,125.32 R177.1@5975,145.08
N17210820: R178.1 U30.6 | length 212.8
  TOP w10: v1(5899.84,100.16) U30.6@5899.84,163.48
  BOTTOM w10: R178.1@5825,145.08 5825,85 5835,75 5874.68,75 v1(5899.84,100.16)
N17210844: C218.1 R173.1 R177.2 U31.3 | length 159.4
  BOTTOM w10: C218.1@5875,204.92 R173.1@5925,204.92 ; U31.3@5929.21,262.6 5929.21,224.21 5925,220 R173.1@5925,204.92 ; R177.2@5975,204.92 R173.1@5925,204.92
N17210846: C219.1 R178.2 R179.1 U31.4 | length 326.9
  BOTTOM w10: R178.2@5825,204.92 5825,234.92 5829,238.92 5829,260.81 U31.4@5830.78,262.6 5830.78,284.22 5785,330 5785,365 5810,390 C219.1@5870.08,390 R179.1@5870.08,440
N17210864: C191.1 C192.1 R172.2 U31.5 | length 307.9
  POWER03 w10: v1(5880,350) 5890.13,339.87 5979.87,339.87 v1(5980,340)
  BOTTOM w10: U31.5@5830.78,337.4 5867.4,337.4 v1(5880,350) ; v1(5980,340) 5990.08,329.92 R172.2@6025,329.92 C191.1@6075,329.92 C192.1@6125,329.92
N17217934: C215.1 R144.1 R145.2 U24.3 | length 159.4
  BOTTOM w10: C215.1@3075,204.92 R144.1@3125,204.92 ; U24.3@3129.21,262.6 3125,258.39 R144.1@3125,204.92 ; R145.2@3175,204.92 R144.1@3125,204.92
N17223082: C161.2 C164.2 D3.1 U22.4 | length 560.8
  TOP w10: U22.4@2501.5,500 2450,500 2445,505 2445,595.35 D3.1@2594.65,745 2649.69,689.96 C161.2@2695,689.96 2734.96,689.96 2740.08,695.08 C164.2@2769.99,695.08
N17223482: C174.2 C177.2 D6.1 U25.4 | length 552
  TOP w10: U25.4@3901.5,500 3850,500 3845,505 3845,600.35 D6.1@3999.65,755 4064.69,689.96 C174.2@4085,689.96 4089.18,694.14 4119.14,694.14 4120.08,695.08 C177.2@4149.99,695.08
N17224001: C190.2 C194.2 D8.1 U29.4 | length 547.9
  TOP w10: U29.4@5301.5,500 5250,500 5245,505 5245,610.35 D8.1@5389.65,755 5454.69,689.96 C190.2@5465,689.96 5534.88,689.96 C194.2@5539.99,695.08
N17453218: C64.1 C65.1 R111.1 U9.1
N17746491: C126.1 C127.1 R125.2 U17.1 | length 206.1
  TOP w20: U17.1@13814,1500 C127.1@13920.08,1500 ; R125.2@13920.08,1450 C127.1@13920.08,1500 ; C126.1@13920.08,1550 C127.1@13920.08,1500
N17747250: C128.1 R126.2 R127.1 U17.2 | length 423.8
  TOP w20: U17.2@13814,1550 13857,1550 13905,1598 13918.08,1598 C128.1@13920.08,1600 R127.1@13920.08,1650 13920.08,1695.08 v1(13925,1700) ; R126.2@14050,1654.92 v1(14050,1700)
  BOTTOM w20: v1(13925,1700) 13955,1670 14020,1670 v1(14050,1700)
N17751858: C129.1 C130.1 R128.1 U17.5 | length 114
  TOP w20: U17.5@13396.68,1650 13455.58,1650 13492.58,1687 v1(13495.34,1687)
N17896613: CL1_A1.1 F5.2 F6.2 R19.2 VAR2.1 VAR3.1 XC7.1 YC9.1
N17896717: R28.2 R29.1 | length 84.8
  BOTTOM w30: R29.1@4880.12,2455 R28.2@4964.88,2455
N17896948: R7.1 R16.1 R25.1 XC1.2 XC4.2 XC7.2 | length 375.6
  BOTTOM w15: R25.1@1600,1005.12 XC7.2@1600,1192.91 ; R7.1@1600,3255.12 XC1.2@1600,3442.91
N17897141: R19.1 R22.2 | length 89.8
  BOTTOM w15: R19.1@1600,605.12 R22.2@1600,694.88
N17897143: R22.1 R25.2 | length 89.8
  BOTTOM w15: R22.1@1600,805.12 R25.2@1600,894.88
N17898200: CL1_A1.5 F1.2 F2.2 R1.2 VAR1.2 VAR2.2 XC1.1 YC2.1
N17898311: CL1_A1.3 F3.2 F4.2 R10.2 VAR1.1 VAR3.2 XC4.1 YC5.1
N17903019: R10.1 R13.2 | length 89.8
  BOTTOM w15: R13.2@1600,1905.12 R10.1@1600,1994.88
N17903021: R13.1 R16.2 | length 89.8
  BOTTOM w15: R16.2@1600,1705.12 R13.1@1600,1794.88
N17903179: R1.1 R4.2 | length 89.8
  BOTTOM w15: R1.1@1600,2855.12 R4.2@1600,2944.88
N17903181: R4.1 R7.2 | length 89.8
  BOTTOM w15: R4.1@1600,3055.12 R7.2@1600,3144.88
N17908016: CL1_A1.2 CL2_A1.1 R20.2 XC8.1 YC8.1
N17908018: CL1_A1.4 CL2_A1.3 R11.2 XC5.1 YC6.1 | length 182.6
  BOTTOM w20: R11.2@4151.12,4143 4330.91,4143 XC5.1@4332.91,4145
N17908020: R8.1 R17.1 R26.1 XC2.2 XC5.2 XC8.2 | length 207
  BOTTOM w15: R26.1@4155.12,1330 XC8.2@4342.09,1330 XC8.2@4362.09,1330
N17908040: R11.1 R14.2 | length 89.8
  BOTTOM w15: R14.2@3951.12,4143 R11.1@4040.88,4143
N17908042: R14.1 R17.2 | length 89.8
  BOTTOM w15: R17.2@3751.12,4143 R14.1@3840.88,4143
N17908062: CL1_A1.6 CL2_A1.5 R2.2 XC2.1 YC3.1
N17908092: R2.1 R5.2 | length 89.8
  BOTTOM w15: R5.2@3950.12,3660 R2.1@4039.88,3660
N17908094: R5.1 R8.2 | length 89.8
  BOTTOM w15: R8.2@3750.12,3660 R5.1@3839.88,3660
N17908164: R20.1 R23.2 | length 89.8
  BOTTOM w15: R20.1@3755.12,1330 R23.2@3844.88,1330
N17908166: R23.1 R26.2 | length 89.8
  BOTTOM w15: R23.1@3955.12,1330 R26.2@4044.88,1330
N17911015: C2.2 Q1.1 R44.1 R50.1 | length 289.8
  BOTTOM w20: R50.1@8640.08,1005 8645,1009.92 C2.2@8645,1075.08 R44.1@8695,1075.08 8740.08,1075.08 8807.6,1142.6 Q1.1@8807.6,1169.76
N17911017: Q2.3 R43.1 R50.2 | length 1066.1
  POWER03 w6: v1(8745,1005) 8595,855 8595,685 8655,625 8725,625 v1(8750,650)
  BOTTOM w6: R43.1@8650,284.92 8650,310 8614.76,345.24 Q2.3@8614.76,380 8637,380 8660,403 8660,435 8685,460 8685,585 v1(8750,650)
  BOTTOM w20: R50.2@8699.92,1005 v1(8745,1005)
N17911032: Q1.3 R42.2 RLY1.2 | length 278.8
  BOTTOM w20: R42.2@8800.12,830 8800.12,875.12 8807.28,882.28 RLY1.2@8807.28,960.67 8807.28,1002.28 8845,1040 Q1.3@8845,1090.24
N17911094: C1.1 R35.2 R36.2 R43.2 R51.2 | length 1592
  POWER03 w6: v1(8595,1005) 8570,980 8570,675 8640,605 8750,605 v1(8795,650)
  BOTTOM w6: R51.2@8579.92,280 R36.2@8579.92,230 8610,230 8614.92,225.08 R43.2@8650,225.08 8680.08,225.08 8695,240 8695,430 8710,445 8710,565 v1(8795,650)
  BOTTOM w20: v1(8595,1005) 8605,1015 8605,1150 8569.88,1185.12 R35.2@8550,1185.12 8550,1205 8581,1236 8609.08,1236 C1.1@8640.08,1205
N17911109: D1.2 R33.1 RLY1.1 | length 261.6
  BOTTOM w20: R33.1@8370,1074.88 8370,996.37 RLY1.1@8405.7,960.67 8410.35,956.02 D1.2@8410.35,830
N17911126: R34.2 R35.1 | length 90
  BOTTOM w20: R34.2@8460,1074.88 R35.1@8550,1074.88
N17911128: R33.2 R34.1 | length 90
  BOTTOM w20: R33.2@8370,1185.12 R34.1@8460,1185.12
N17911225: C5.2 Q4.1 R62.1 R63.1 | length 289.8
  BOTTOM w20: R63.1@8640.08,3620 8645,3624.92 C5.2@8645,3690.08 R62.1@8695,3690.08 8740.08,3690.08 8807.6,3757.6 Q4.1@8807.6,3784.76
N17911227: Q5.3 R61.1 R63.2 R201.2 | length 3700.3
  POWER03 w6: v1(8700,650) 8700,700 9210,1210 9210,1765 8725,2250 8725,2300 v1(8745,2320) 8725,2340 8725,3600 v1(8745,3620)
  BOTTOM w6: R61.1@8650,534.92 8650,555 8614.76,590.24 Q5.3@8614.76,630 8680,630 v1(8700,650)
  BOTTOM w20: R201.2@8699.92,2320 v1(8745,2320) ; R63.2@8699.92,3620 v1(8745,3620)
N17911239: Q4.3 R60.2 RLY2.2 | length 278.8
  BOTTOM w20: R60.2@8800.12,3445 8800.12,3543.5 8807.28,3550.66 RLY2.2@8807.28,3575.66 8807.28,3667.53 Q4.3@8845,3705.24
N17911299: C4.1 R56.2 R57.2 R61.2 R64.2 | length 4091.4
  POWER03 w6: v1(8625,700) 8660,700 9180,1220 9180,1765 8695,2250 8695,3820 v1(8645,3870)
  BOTTOM w6: v1(8625,700) 8570,645 8570,615 8579.92,605.08 R64.2@8579.92,530 R57.2@8579.92,480 8645.08,480 R61.2@8650,475.08
  BOTTOM w20: R56.2@8570,3800.12 8620.19,3800.12 C4.1@8640.08,3820 8640.08,3865.08 v1(8645,3870)
N17911323: D2.2 R54.1 RLY2.1 | length 261.6
  BOTTOM w20: R54.1@8370,3689.88 8370,3611.36 RLY2.1@8405.7,3575.66 8410.35,3571.01 D2.2@8410.35,3445
N17911339: R55.2 R56.1 | length 100
  BOTTOM w20: R55.2@8470,3689.88 R56.1@8570,3689.88
N17911341: R54.2 R55.1 | length 100
  BOTTOM w20: R54.2@8370,3800.12 R55.1@8470,3800.12
N17913837: R37.2 R38.1 | length 84.8
  BOTTOM w30: R38.1@4880.12,2230 R37.2@4964.88,2230
N17913950: R45.2 R46.1 | length 84.8
  BOTTOM w30: R46.1@4880.12,1910 R45.2@4964.88,1910
N17916039: C19.1 C20.1 C21.1 C32.1 C33.1 C206.1 C207.1 C208.1 C209.1 C210.1 F7.1 F8.1 Q7.1 Q8.1 Q9.1 R72.2 R73.2 | length 6391.4
  BOTTOM w40: R72.2@5982.76,2090.87 R73.2@6077.76,2090.87 6145.87,2090.87 6315,2260 6315,3230 6130,3415 6130,4535 6380,4785 8155,4785 8310,4630 9235,4630 9375.78,4770.78 F7.1@9375.78,4936.43
N17916066: L2.1 Q7.2 Q11.1
N17916108: L3.1 Q8.2 Q10.1
N17916243: L4.1 Q9.2 Q12.1
N17916612: R72.1 R78.2 | length 89.8
  BOTTOM w15: R78.2@5982.76,1890.87 R72.1@5982.76,1980.63
N17916616: R78.1 R80.2 | length 89.8
  BOTTOM w15: R80.2@5982.76,1690.87 R78.1@5982.76,1780.63
N17916654: R77.1 R79.2 | length 89.8
  BOTTOM w15: R79.2@6077.76,1690.87 R77.1@6077.76,1780.63
N17916656: R79.1 R81.2 | length 89.8
  BOTTOM w15: R81.2@6077.76,1490.87 R79.1@6077.76,1580.63
N17919278: R83.1 R89.2 | length 89.8
  BOTTOM w15: R89.2@5982.76,1290.87 R83.1@5982.76,1380.63
N17919280: R89.1 R92.2 | length 89.8
  BOTTOM w15: R92.2@5982.76,1090.87 R89.1@5982.76,1180.63
N17919331: R84.1 R90.2 | length 89.8
  BOTTOM w15: R90.2@6077.76,1090.87 R84.1@6077.76,1180.63
N17919333: R90.1 R93.2 | length 89.8
  BOTTOM w15: R93.2@6077.76,890.87 R90.1@6077.76,980.63
N17919338: R80.1 R83.2 | length 89.8
  BOTTOM w15: R83.2@5982.76,1490.87 R80.1@5982.76,1580.63
N17919341: R81.1 R84.2 | length 89.8
  BOTTOM w15: R84.2@6077.76,1290.87 R81.1@6077.76,1380.63
N17920487: C10.2 C11.2 C13.2 C16.2 C17.2 C23.1 C24.1 C27.1 C28.1 C31.1 R208.1 R209.1 R210.2 R211.2 R219.1 R221.1 R222.2 R223.2 R230.1 R233.1 R234.2 R237.2 | length 3069.9
  BOTTOM w15: C27.1@2035,6383.15 2093.27,6324.88 R211.2@2310,6324.88 ; C17.2@2760,5501.85 2818.27,5560.12 R219.1@3035,5560.12 ; 3569.88,6324.88 R222.2@3735,6324.88 ; C10.2@4185,5501.85 4243.27,5560.12 R221.1@4460,5560.12 ; C23.1@4885,6383.15 4943.27,6324.88 R237.2@5160,6324.88 ; C11.2@5610,5501.85 5668.27,5560.12 R233.1@5885,5560.12 ; C24.1@6310,6383.15 6368.27,6324.88 R223.2@6585,6324.88 ; C13.2@7035,5526.85 7093.27,5585.12 R230.1@7310,5585.12 R208.1@7465,5585.12 ; C31.1@7735,6383.15 7793.27,6324.88 R234.2@8010,6324.88 R210.2@8150,6324.88 ; 8618.27,5585.12 R209.1@8835,5585.12
N17922701: C112.1 C113.1 R117.2 U15.1 | length 206.1
  TOP w20: U15.1@13814,5350 C113.1@13920.08,5350 ; R117.2@13920.08,5300 C113.1@13920.08,5350 ; C112.1@13920.08,5400 C113.1@13920.08,5350
N17922735: C114.1 R118.2 R119.1 U15.2 | length 423.8
  TOP w20: U15.2@13814,5400 13855,5400 13903,5448 13918.08,5448 C114.1@13920.08,5450 R119.1@13920.08,5500 13920.08,5525 13920.08,5545.08 v1(13925,5550) ; R118.2@14050,5504.92 v1(14050,5550)
  BOTTOM w20: v1(13925,5550) 13955,5520 14020,5520 v1(14050,5550)
N17922803: C115.1 C116.1 R120.1 U15.5 | length 114
  TOP w20: U15.5@13396.68,5500 13458.34,5500 v1(13495.34,5537)
N17923309: C119.1 C120.1 R121.2 U16.1 | length 206.1
  TOP w20: U16.1@13814,6375 C120.1@13920.08,6375 ; R121.2@13920.08,6325 C120.1@13920.08,6375 ; C119.1@13920.08,6425 C120.1@13920.08,6375
N17923353: C121.1 R122.2 R123.1 U16.2 | length 423.8
  TOP w20: U16.2@13814,6425 13855,6425 13903,6473 13918.08,6473 C121.1@13920.08,6475 R123.1@13920.08,6525 13920.08,6550 13920.08,6570.08 v1(13925,6575) ; R122.2@14050,6529.92 v1(14050,6575)
  BOTTOM w20: v1(13925,6575) 13955,6545 14020,6545 v1(14050,6575)
N17923421: C122.1 C123.1 R124.1 U16.5 | length 114
  TOP w20: U16.5@13396.68,6525 13458.34,6525 v1(13495.34,6562)
N17924447: C133.1 C134.1 R129.2 U18.1 | length 206.1
  TOP w20: U18.1@13814,2525 C134.1@13920.08,2525 ; R129.2@13920.08,2475 C134.1@13920.08,2525 ; C133.1@13920.08,2575 C134.1@13920.08,2525
N17924481: C135.1 R130.2 R131.1 U18.2 | length 423.8
  TOP w20: U18.2@13814,2575 13858,2575 13906,2623 13918.08,2623 C135.1@13920.08,2625 R131.1@13920.08,2675 13920.08,2720.08 v1(13925,2725) ; R130.2@14050,2679.92 v1(14050,2725)
  BOTTOM w20: v1(13925,2725) 13955,2695 14020,2695 v1(14050,2725)
N17924549: C136.1 C137.1 R132.1 U18.5 | length 114
  TOP w20: U18.5@13396.68,2675 13458.34,2675 v1(13495.34,2712)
